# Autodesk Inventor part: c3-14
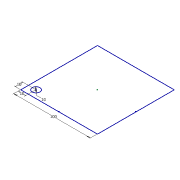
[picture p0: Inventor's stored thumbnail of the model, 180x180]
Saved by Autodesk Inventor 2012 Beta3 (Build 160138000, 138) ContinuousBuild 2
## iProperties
Created: 2010-11
Part Number: c3-14
Material: Default
Document SubType Name: Modeling
Designer: Beta-8540w
Density: 1 g/cm^3
Author: Beta-8540w
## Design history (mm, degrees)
sketch "Sketch1"
  geometry: L1 (-50, -50)-(50, -50); L2 (50, -50)-(50, 50); L3 (50, 50)-(-50, 50); L4 (-50, 50)-(-50, -50); C1 r 5 at (-40, -40); 3 further points
  constraints: 8 end point, 3 perpendicular, 2 midpoint, 1 centre point, 1 horizontal, 1 horizontal alignment, 1 parallel, 1 vertical alignment
  dimensions: "d0" = 100 distance of L1.start L1.end; "d3" = 10 diameter of C1; "d4" = 10 distance from line of L4 C1.centre; "d5" = 10 distance from line of L1 C1.centre
